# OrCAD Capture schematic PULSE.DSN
size A
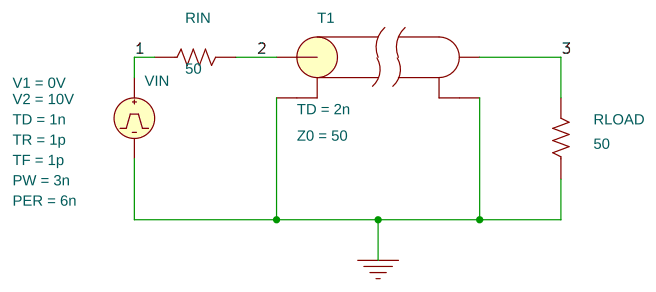
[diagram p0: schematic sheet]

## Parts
RIN  50  [AX/RC05]
RLOAD  50  [AX/RC05]
T1  T
VIN  VPULSE

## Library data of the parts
RIN RLOAD = R
T1 = T: TD: 2n; Z0: 50
VIN = VPULSE: PER: 6n; PW: 3n; TD: 1n; TF: 1p; TR: 1p; V1: 0V; V2: 10V

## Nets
0: RLOAD.1 T1.2(A-) T1.4(B-) VIN.2(-)
1: RIN.1 VIN.1(+)
2: RIN.2 T1.1(A+)
3: RLOAD.2 T1.3(B+)
